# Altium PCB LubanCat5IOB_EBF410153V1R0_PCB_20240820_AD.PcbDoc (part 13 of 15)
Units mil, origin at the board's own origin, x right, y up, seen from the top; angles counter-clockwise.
Board outline 6811.02 x 4055.12 mil, 6 copper layers (TOP, GND02, ART03, ART04, PWR05, BOTTOM), stack 59.279 mil thick; 981 components, 783 nets, 3627 pads, 2669 vias.
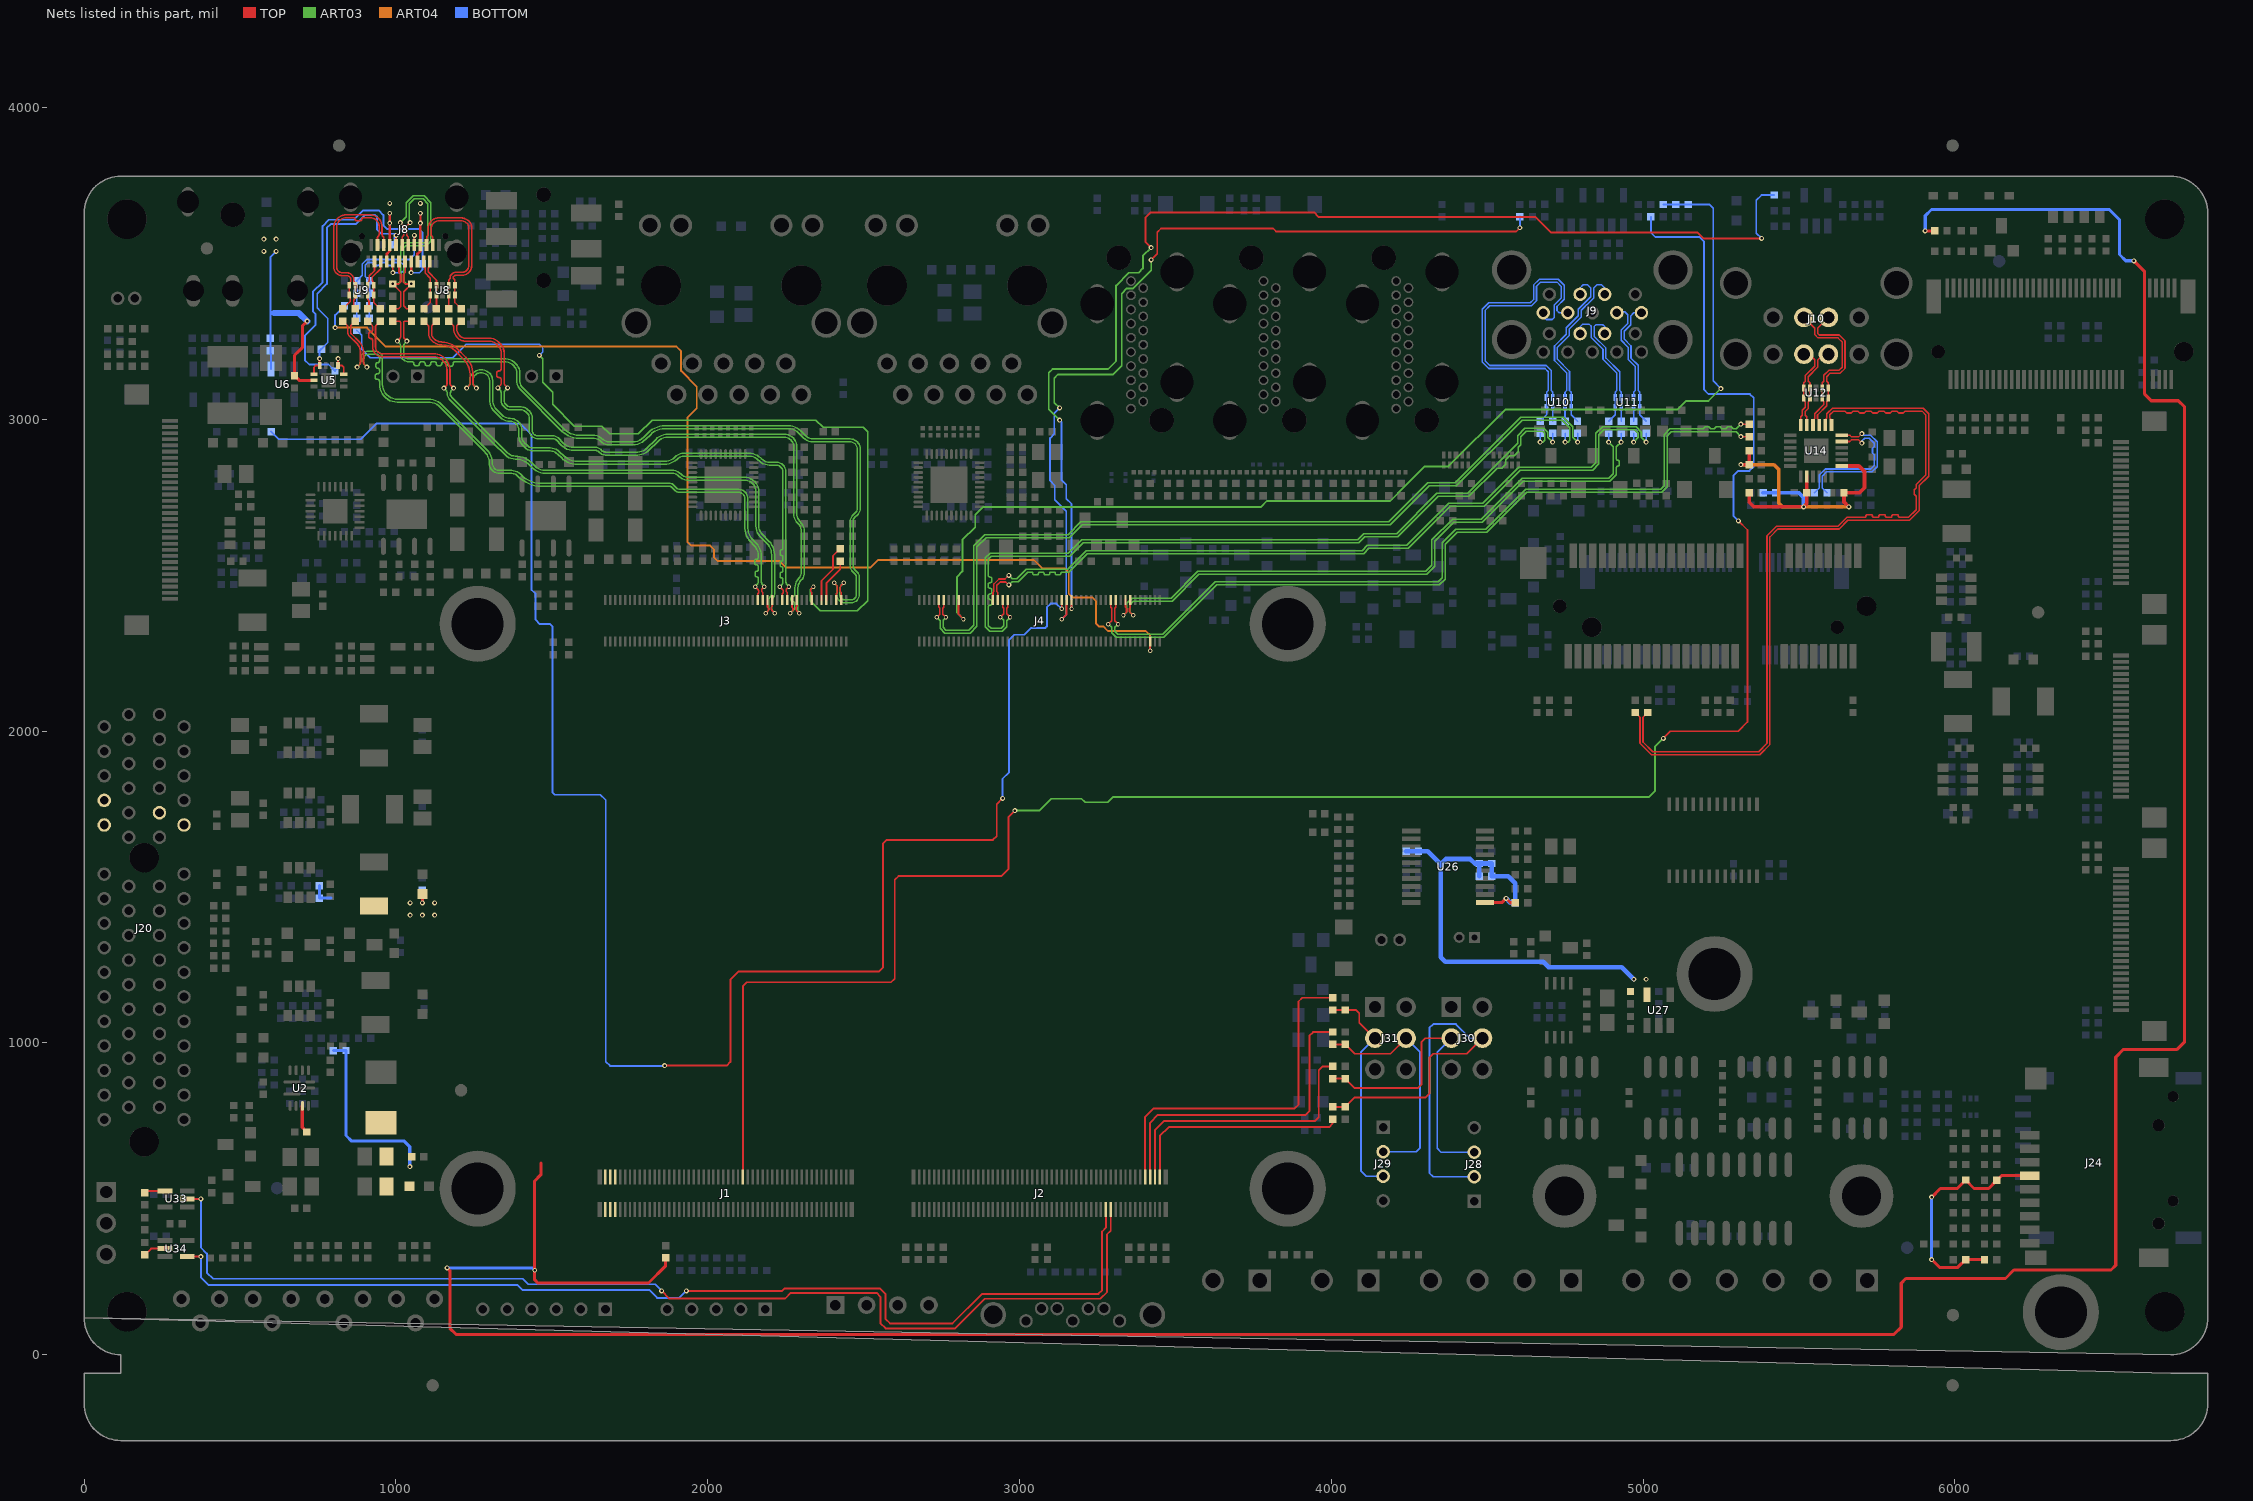
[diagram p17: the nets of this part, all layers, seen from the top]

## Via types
v1: diameter 16, hole 8, TOP to BOTTOM, 2357 vias
v2: diameter 14, hole 8, TOP to BOTTOM, 308 vias
v3: diameter 20, hole 10, TOP to BOTTOM, 4 vias

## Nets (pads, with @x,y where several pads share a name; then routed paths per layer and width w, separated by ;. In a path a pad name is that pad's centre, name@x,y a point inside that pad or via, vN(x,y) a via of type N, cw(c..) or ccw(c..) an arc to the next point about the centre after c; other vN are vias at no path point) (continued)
TYPEC0_SBU2: C85.2 J3.86 | length 2818.1
  TOP w5.2: J3.86@2333.57,2420.74 2333.57,2444.59 2330.39,2447.76 2330.39,2454.48 v2(2339.39,2463.48)
  ART03 w4.5: v1(1460.17,3205) 1470.5,3194.67 1470.5,3119.06 1502.5,3087.06 1502.5,3048.06 1572.06,2978.5 1661.06,2978.5 1686.06,2953.5 1777.94,2953.5 1821.94,2997.5 2347.06,2997.5 2370.06,2974.5 2499.06,2974.5 2513,2960.56 2513,2418 2480.5,2385.5 2361.5,2385.5 2329.44,2417.56 2329.44,2453.53 v2(2339.39,2463.48)
  BOTTOM w5.2: C85.2@875,3284.69 890.3,3269.39 890.3,3224.7 918,3197 1182.29,3197 1225.78,3240.49 1460.15,3240.49 1470.55,3230.09 1470.55,3215.38 v1(1460.17,3205)
TYPEC0_SBU2_DC: J4.95 R94.2 | length 3671.8
  TOP w6: v2(3418.91,2258.14) J4.95@3418.91,2286.88
  ART04 w6: v1(805.32,3294.05) 906.95,3294.05 967.63,3233.37 1900,3233.37 1915,3218.37 1915,3155 1965,3105 1965,3035 1935,3005 1935,2607 1947,2595 2008,2595 2020,2583 2020,2557 2032,2545 2231,2545 2251,2525 2523,2525 2547,2549 3046,2549 3073,2522 3146,2522 3158,2510 3158,2441 3170,2429 3234,2429 3246,2417 3246,2345 3255,2336 3268,2336 3283,2321 3404.91,2321 3418.91,2307 v2(3418.91,2258.14)
  BOTTOM w6: v1(805.32,3294.05) 805.32,3334.37 R94.2@835.32,3364.37
TYPEC0_SSRX1N: J3.80 R86.2 | length 2059.6
  TOP w5.2: R86.2@1210,3314.69 1196.83,3301.52 ccw(c1201.98,3296.37) 1194.7,3296.37 1194.7,3291.75 ccw(c1229.03,3291.75) 1204.76,3267.47 ccw(c1222.8,3285.51) 1222.8,3260 1299.54,3260 cw(c1299.54,3217.13) 1329.85,3247.44 1334.84,3242.45 cw(c1304.53,3212.14) 1347.4,3212.14 1347.4,3116.49 ccw(c1358.84,3116.49) 1350.75,3108.4 v1(1358.15,3101) ; 2285.82,2386.32 v2(2294.15,2378) ; 2285.83,2386.32 cw(c2292.28,2392.78) 2283.15,2392.78 2283.15,2397.61 2286.32,2400.78 J3.80@2286.32,2420.74
  ART03 w4.5: v1(1358.15,3101) 1352.26,3095.11 ccw(c1364.96,3082.41) 1347,3082.41 1347,3060.39 ccw(c1362.41,3060.39) 1351.51,3049.48 1356.92,3044.08 ccw(c1367.82,3054.98) 1367.82,3039.57 1402.55,3039.57 cw(c1402.55,3010.87) 1422.84,3031.16 1428.6,3025.4 cw(c1408.31,3005.11) 1437,3005.12 1437,2966.41 ccw(c1456.41,2966.41) 1456.41,2947 1504.68,2947 cw(c1504.68,2924.5) 1520.59,2940.41 1537.47,2923.53 ccw(c1570.13,2956.18) 1570.13,2910 1640.68,2910 cw(c1640.68,2887.5) 1656.59,2903.41 1660.31,2899.7 ccw(c1671.64,2911.03) 1671.64,2895 1775.37,2895 ccw(c1775.37,2936.52) 1804.72,2907.16 1832.7,2935.14 cw(c1873.41,2894.42) 1873.41,2952 2246.12,2952 cw(c2246.11,2912.62) 2273.96,2940.46 cw(c2246.12,2912.61) 2285.5,2912.62 2285.5,2698.32 ccw(c2321.28,2698.32) 2295.98,2673.02 cw(c2262.14,2639.18) 2310,2639.18 2310,2509.17 cw(c2273.22,2509.17) 2299.23,2483.16 ; v2(2294.15,2378) cw(c2305.37,2389.22) 2289.5,2389.22 2289.5,2459.68 cw(c2322.7,2459.68) 2299.22,2483.15
TYPEC0_SSRX1P: J3.78 R85.2 | length 2095
  TOP w5.2: R85.2@1170,3314.69 1183.17,3301.52 cw(c1178.02,3296.37) 1185.3,3296.37 1185.3,3291.75 ccw(c1229.03,3291.75) 1198.11,3260.83 ccw(c1222.8,3285.51) 1222.8,3250.6 1299.54,3250.6 cw(c1299.54,3217.13) 1323.2,3240.8 1328.2,3235.8 cw(c1304.53,3212.14) 1338,3212.14 1338,3162.49 cw(c1330.5,3162.49) 1330.5,3154.99 ccw(c1330.5,3147.49) 1323,3147.49 1323,3141.69 ccw(c1330.5,3141.69) 1330.5,3134.19 cw(c1330.5,3126.69) 1338,3126.69 1338,3116.49 cw(c1326.56,3116.49) 1334.65,3108.4 v1(1327.25,3101) ; v2(2264.75,2378) 2271.74,2384.99 ccw(c2266.9,2389.84) 2273.75,2389.84 2273.75,2393.71 2270.57,2396.89 J3.78@2270.57,2420.74
  ART03 w4.5: v1(1327.25,3101) 1332.69,3095.55 cw(c1321.08,3083.95) 1337.5,3083.95 1337.5,3060.39 ccw(c1362.41,3060.38) 1344.8,3042.77 1350.2,3037.36 ccw(c1367.82,3054.98) 1367.82,3030.07 1402.55,3030.07 cw(c1402.55,3010.87) 1416.12,3024.44 1421.88,3018.69 cw(c1408.31,3005.11) 1427.5,3005.11 1427.5,2966.41 ccw(c1456.41,2966.41) 1456.41,2937.5 1504.68,2937.5 cw(c1504.68,2924.5) 1513.87,2933.69 1530.76,2916.81 ccw(c1570.13,2956.18) 1570.13,2900.5 1640.68,2900.5 cw(c1640.68,2887.5) 1649.87,2896.69 1653.59,2892.98 ccw(c1671.64,2911.03) 1671.64,2885.5 1775.37,2885.5 ccw(c1775.37,2936.52) 1811.44,2900.44 1839.42,2928.42 cw(c1873.41,2894.42) 1873.41,2942.5 2246.11,2942.5 cw(c2246.11,2912.62) 2267.24,2933.75 cw(c2246.12,2912.61) 2276,2912.61 2276,2698.32 ccw(c2321.28,2698.32) 2289.26,2666.3 cw(c2262.14,2639.18) 2300.5,2639.18 2300.5,2509.17 cw(c2273.22,2509.17) 2292.51,2489.88 ; v2(2264.75,2378) 2276.14,2389.4 ccw(c2266.84,2398.7) 2280,2398.7 2280,2408.2 ccw(c2273.5,2408.2) 2273.5,2414.7 cw(c2273.5,2421.2) 2267,2421.2 2267,2426.2 cw(c2273.5,2426.2) 2273.5,2432.7 ccw(c2273.5,2439.2) 2280,2439.2 2280,2459.68 cw(c2322.7,2459.68) 2292.51,2489.87
TYPEC0_SSRX2N: J3.70 R91.2 | length 2034.3
  TOP w5.2: R91.2@950,3314.69 936.83,3301.52 ccw(c941.98,3296.37) 934.7,3296.37 934.7,3231.87 ccw(c956.17,3231.87) 940.99,3216.69 ccw(c956.17,3231.87) 956.17,3210.4 1121.13,3210.4 cw(c1121.13,3160.99) 1156.07,3195.93 1158.93,3193.07 cw(c1123.99,3158.14) 1173.4,3158.14 1173.4,3114.77 ccw(c1180.68,3114.77) 1175.53,3109.62 v1(1185.15,3100) ; J3.70@2207.58,2420.74 2207.58,2400.78 2204.41,2397.61 2204.41,2392.78 ccw(c2213.54,2392.78) 2207.09,2386.32 v2(2215.41,2378)
  ART03 w4.5: v1(1185.15,3100) 1179.48,3094.33 ccw(c1191.64,3082.18) 1174.45,3082.18 1174.45,3081.31 ccw(c1188.37,3081.31) 1178.53,3071.47 1321.03,2928.97 1357.39,2892.61 ccw(c1383,2918.21) 1383,2882 cw(c1383,2807.16) 1435.92,2860.08 1446.31,2849.7 ccw(c1478.16,2881.55) 1478.16,2836.5 1885.52,2836.5 cw(c1885.52,2795.51) 1914.51,2824.49 ccw(c1939.84,2849.82) 1939.84,2814 2118.09,2814 cw(c2118.09,2768.09) 2164,2768.09 2164,2657.95 ccw(c2202.51,2657.95) 2175.28,2630.72 2196.4,2609.6 cw(c2152.7,2565.9) 2214.5,2565.9 2214.5,2439.37 cw(c2194.43,2439.37) 2208.62,2425.19 ccw(c2216.25,2417.55) 2205.46,2417.55 2205.46,2394.54 ccw(c2221.36,2394.54) 2210.12,2383.29 v2(2215.41,2378)
TYPEC0_SSRX2P: J3.68 R89.2 | length 2046.5
  TOP w5.2: R89.2@910,3314.69 923.17,3301.52 cw(c918.02,3296.37) 925.3,3296.37 925.3,3286.17 cw(c919.15,3286.17) 919.15,3280.02 ccw(c919.15,3273.87) 913,3273.87 913,3265.37 ccw(c919.15,3265.37) 919.15,3259.22 cw(c919.15,3253.07) 925.3,3253.07 925.3,3231.87 ccw(c956.17,3231.87) 934.34,3210.04 ccw(c956.17,3231.87) 956.17,3201 1121.13,3201 cw(c1121.13,3160.99) 1149.42,3189.28 1152.28,3186.42 cw(c1123.99,3158.14) 1164,3158.14 1164,3115.36 cw(c1150.48,3115.36) 1160.04,3105.79 v1(1154.25,3100) ; v2(2186.01,2378) 2193,2384.99 ccw(c2188.16,2389.84) 2195.01,2389.84 2195.01,2393.71 2191.84,2396.89 J3.68@2191.84,2420.74
  ART03 w4.5: v1(1154.25,3100) 1159.92,3094.33 cw(c1147.76,3082.18) 1164.95,3082.18 1164.95,3081.31 ccw(c1188.37,3081.31) 1171.81,3064.76 1314.31,2922.25 1350.68,2885.89 ccw(c1383,2918.21) 1383,2872.5 cw(c1383,2807.16) 1429.2,2853.36 1439.59,2842.98 ccw(c1478.16,2881.55) 1478.16,2827 1885.52,2827 cw(c1885.52,2795.51) 1907.79,2817.78 ; 1907.79,2817.77 ccw(c1939.84,2849.82) 1939.84,2804.5 2118.09,2804.5 cw(c2118.09,2768.09) 2154.5,2768.09 2154.5,2657.95 ccw(c2202.51,2657.95) 2168.56,2624 2189.68,2602.88 cw(c2152.7,2565.9) 2205,2565.9 2205,2439.37 cw(c2194.44,2439.38) 2201.9,2431.9 ccw(c2216.26,2417.55) 2195.96,2417.55 2195.96,2394.54 cw(c2180.06,2394.54) 2191.3,2383.29 v2(2186.01,2378)
TYPEC0_SSTX1N: C80.2 J3.76 | length 1996.9
  TOP w5.2: C80.2@1090,3314.69 1103.17,3301.52 cw(c1098.02,3296.37) 1105.3,3296.37 1105.3,3274.16 ccw(c1133.69,3274.16) 1113.61,3254.09 1116.64,3251.06 ccw(c1146.73,3281.16) 1146.73,3238.6 cw(c1146.74,3179.77) 1188.34,3221.37 1218.12,3191.58 cw(c1170.14,3143.6) 1238,3143.6 1238,3115.49 cw(c1226.56,3115.49) 1234.65,3107.4 v1(1227.25,3100) ; J3.76@2254.83,2420.74 2254.83,2444.59 2251.65,2447.76 2251.65,2451.64 cw(c2258.5,2451.64) 2253.66,2456.48 v2(2260.65,2463.48)
  ART03 w4.5: v1(1227.25,3100) 1232.92,3105.67 ccw(c1220.76,3117.82) 1237.95,3117.82 1237.95,3128.07 cw(c1262.87,3128.07) 1245.25,3145.68 1248.77,3149.2 cw(c1272.78,3125.19) 1272.78,3159.15 cw(c1272.79,3119.31) 1300.95,3147.48 ; 1300.98,3147.46 cw(c1279.2,3125.68) 1310,3125.68 1310,3064.26 ccw(c1357.86,3064.26) 1324.02,3030.42 1340.7,3013.74 ccw(c1366.62,3039.66) 1366.62,3003 cw(c1366.62,2965.62) 1404,2965.62 1404,2944.82 ccw(c1432.54,2944.82) 1412.36,2924.64 1420.64,2916.36 ccw(c1440.82,2936.54) 1440.82,2908 1494.74,2908 cw(c1494.74,2863.92) 1525.91,2895.09 1538.09,2882.91 ccw(c1581.33,2926.15) 1581.33,2865 1861.13,2865 ccw(c1861.13,2912.97) 1895.05,2879.05 cw(c1923.89,2850.21) 1923.89,2891 2133.1,2891 cw(c2133.1,2839.48) 2169.53,2875.91 ; 2169.53,2875.91 2172.08,2873.35 ccw(c2198.28,2899.55) 2198.28,2862.5 2221.82,2862.5 cw(c2221.82,2836.72) 2240.05,2854.95 2243.15,2851.85 cw(c2224.92,2833.61) 2250.7,2833.62 2250.7,2480.01 ccw(c2266.6,2480.01) 2255.36,2468.77 v2(2260.65,2463.48)
TYPEC0_SSTX1P: C79.2 J3.74 | length 1999.6
  TOP w5.2: C79.2@1130,3314.69 1116.83,3301.52 ccw(c1121.98,3296.37) 1114.7,3296.37 1114.7,3274.16 ccw(c1133.69,3274.16) 1120.26,3260.74 1123.29,3257.71 ccw(c1146.73,3281.15) 1146.73,3248 cw(c1146.74,3179.77) 1194.99,3228.02 1224.77,3198.23 cw(c1170.14,3143.6) 1247.4,3143.6 1247.4,3115.49 ccw(c1258.84,3115.49) 1250.75,3107.4 v1(1258.15,3100) ; v2(2231.25,2463.48) 2239.58,2455.15 cw(c2233.12,2448.69) 2242.25,2448.69 2242.25,2443.87 2239.08,2440.7 J3.74@2239.08,2420.74
  ART03 w4.5: v1(1258.15,3100) 1252.48,3105.67 cw(c1264.64,3117.82) 1247.45,3117.82 1247.45,3128.07 cw(c1262.87,3128.07) 1251.96,3138.97 1255.48,3142.49 cw(c1272.78,3125.19) 1272.78,3149.65 cw(c1272.78,3119.31) 1294.24,3140.76 cw(c1279.2,3125.68) 1300.5,3125.68 1300.5,3064.26 ccw(c1357.86,3064.26) 1317.3,3023.7 1333.98,3007.02 ccw(c1366.62,3039.66) 1366.62,2993.5 cw(c1366.62,2965.62) 1394.5,2965.62 1394.5,2944.82 ccw(c1432.54,2944.82) 1405.64,2917.92 1413.92,2909.64 ccw(c1440.82,2936.54) 1440.82,2898.5 1494.74,2898.5 cw(c1494.74,2863.92) 1519.19,2888.37 1531.37,2876.19 ccw(c1581.33,2926.15) 1581.33,2855.5 1861.13,2855.5 ccw(c1861.13,2912.97) 1901.77,2872.33 cw(c1923.89,2850.22) 1923.89,2881.5 2133.1,2881.5 cw(c2133.1,2839.48) 2162.81,2869.19 2165.36,2866.64 ccw(c2198.28,2899.55) 2198.28,2853 2221.82,2853 cw(c2221.82,2836.72) 2233.33,2848.23 2236.43,2845.13 cw(c2224.92,2833.61) 2241.2,2833.61 2241.2,2585.86 cw(c2236.6,2585.86) 2236.6,2581.26 ccw(c2236.6,2576.66) 2232,2576.66 2232,2567.86 ccw(c2236.6,2567.86) 2236.6,2563.26 cw(c2236.6,2558.66) 2241.2,2558.66 2241.2,2549.86 cw(c2236.6,2549.86) 2236.6,2545.26 ccw(c2236.6,2540.66) 2232,2540.66 2232,2531.86 ccw(c2236.6,2531.86) 2236.6,2527.26 cw(c2236.6,2522.66) 2241.2,2522.66 2241.2,2513.86 cw(c2236.6,2513.86) 2236.6,2509.26 ccw(c2236.6,2504.66) 2232,2504.66 2232,2495.86 ccw(c2236.6,2495.86) 2236.6,2491.26 cw(c2236.6,2486.66) 2241.2,2486.66 2241.2,2477.16 cw(c2232.2,2477.16) 2238.57,2470.79 v2(2231.25,2463.48)
TYPEC0_SSTX2N: C83.2 J3.66 | length 2071.9
  TOP w5.2: C83.2@830,3314.69 843.17,3301.52 cw(c838.02,3296.37) 845.3,3296.37 845.3,3280.61 ccw(c865.1,3280.61) 851.1,3266.61 875.76,3241.95 cw(c849.59,3215.78) 886.6,3215.78 886.6,3182.54 cw(c875.16,3182.54) 883.25,3174.45 v1(875.85,3167.05) ; J3.66@2176.09,2420.74 2176.09,2444.59 2172.91,2447.76 2172.91,2451.64 cw(c2179.76,2451.64) 2174.92,2456.48 v2(2181.91,2463.48)
  ART03 w4.5: v1(875.85,3167.05) 881.52,3172.72 ccw(c869.36,3184.87) 886.55,3184.87 886.55,3194 cw(c910.55,3194) 910.55,3218 936.1,3218 cw(c936.1,3197.1) 957,3197.1 957,3112.33 ccw(c1004.83,3112.33) 1004.83,3064.5 1102.84,3064.5 cw(c1102.84,2999.08) 1149.1,3045.34 1290.58,2903.86 cw(c1246.11,2859.39) 1309,2859.39 ccw(c1332.38,2859.39) 1315.85,2842.85 ccw(c1332.39,2859.38) 1332.39,2836 1371.19,2836 cw(c1371.19,2797.83) 1398.18,2824.82 1401.39,2821.61 ccw(c1465.63,2885.84) 1465.63,2795 1875.68,2795 cw(c1875.68,2772.5) 1891.59,2788.41 1900.45,2779.55 ccw(c1911.43,2790.51) 1911.43,2775 2099.17,2775 cw(c2099.17,2745.17) 2129,2745.17 2129,2650.87 ccw(c2181.79,2650.87) 2144.46,2613.54 2155.11,2602.89 cw(c2114.43,2562.21) 2171.96,2562.21 2171.96,2480.01 ccw(c2187.86,2480.01) 2176.62,2468.77 v2(2181.91,2463.48)
TYPEC0_SSTX2P: C82.2 J3.64 | length 2098.1
  TOP w5.2: C82.2@870,3314.69 856.83,3301.52 ccw(c861.98,3296.37) 854.7,3296.37 854.7,3280.61 ccw(c865.1,3280.61) 857.75,3273.25 882.41,3248.59 cw(c849.59,3215.78) 896,3215.78 896,3182.54 ccw(c907.44,3182.54) 899.35,3174.45 v1(906.75,3167.05) ; v2(2152.51,2463.48) 2160.84,2455.15 cw(c2154.38,2448.69) 2163.51,2448.69 2163.51,2443.87 2160.34,2440.7 J3.64@2160.34,2420.74
  ART03 w4.5: v1(906.75,3167.05) 901.08,3172.72 cw(c913.24,3184.87) 896.05,3184.87 896.05,3194 cw(c910.55,3194) 910.55,3208.5 936.1,3208.5 cw(c936.1,3197.1) 947.5,3197.1 947.5,3187.6 cw(c941.75,3187.6) 941.75,3181.85 ccw(c941.75,3176.1) 936,3176.1 936,3169.6 ccw(c941.75,3169.6) 941.75,3163.85 cw(c941.75,3158.1) 947.5,3158.1 947.5,3151.6 cw(c941.75,3151.6) 941.75,3145.85 939.75,3145.85 ccw(c939.75,3140.1) 934,3140.1 934,3133.6 ccw(c939.75,3133.6) 939.75,3127.85 941.75,3127.85 cw(c941.75,3122.1) 947.5,3122.1 947.5,3112.33 ccw(c1004.83,3112.33) 1004.83,3055 1102.84,3055 cw(c1102.84,2999.08) 1142.38,3038.62 1283.86,2897.14 cw(c1246.11,2859.39) 1299.5,2859.39 ccw(c1332.38,2859.39) 1309.13,2836.13 ccw(c1332.38,2859.38) 1332.38,2826.5 1371.19,2826.5 cw(c1371.19,2797.83) 1391.46,2818.1 1394.67,2814.89 ccw(c1465.63,2885.84) 1465.63,2785.5 1875.68,2785.5 cw(c1875.68,2772.5) 1884.87,2781.69 1893.74,2772.83 ccw(c1911.43,2790.51) 1911.43,2765.5 ; 1911.42,2765.5 2099.17,2765.5 cw(c2099.17,2745.17) 2119.5,2745.17 2119.5,2650.87 ccw(c2181.79,2650.86) 2137.74,2606.82 2148.39,2596.17 cw(c2114.43,2562.2) 2162.46,2562.21 2162.46,2556.94 cw(c2156.73,2556.94) 2156.73,2551.21 ccw(c2156.73,2545.48) 2151,2545.48 2151,2538.94 ccw(c2156.73,2538.94) 2156.73,2533.21 cw(c2156.73,2527.48) 2162.46,2527.48 2162.46,2517.98 cw(c2157.23,2517.98) 2157.23,2512.74 ccw(c2157.23,2507.51) 2152,2507.51 2152,2499.98 ccw(c2157.23,2499.98) 2157.23,2494.74 cw(c2157.23,2489.51) 2162.46,2489.51 2162.46,2480.01 cw(c2146.56,2480.01) 2157.81,2468.77 v2(2152.51,2463.48)
TYPEC0_USB20_OTG_DM: J3.98 R82.2 | length 2506.4
  TOP w5.2: R82.2@990,3314.69 1010.1,3314.69 cw(c1010.1,3309.49) 1015.3,3309.49 1015.3,3266.42 cw(c1003.86,3266.42) 1011.95,3258.33 v1(1004.55,3250.92) ; J3.98@2428.06,2420.74 2428.06,2444.59 2424.88,2447.76 2424.88,2457.22 cw(c2442.41,2457.22) 2430.01,2469.61 v2(2435.88,2475.48)
  ART03 w4.5: v1(1004.55,3250.92) 1010.22,3245.25 cw(c998.06,3233.1) 1015.25,3233.1 1015.25,3208.39 ccw(c1036.64,3208.39) 1021.51,3193.26 ccw(c1041.47,3213.22) 1041.47,3185 1050.97,3185 cw(c1050.97,3178.5) 1057.47,3178.5 ccw(c1063.97,3178.5) 1063.97,3172 1068.97,3172 ccw(c1068.97,3178.5) 1075.47,3178.5 cw(c1081.97,3178.5) 1081.97,3185 1086.97,3185 cw(c1086.97,3178.5) 1093.47,3178.5 ccw(c1099.97,3178.5) 1099.97,3172 1104.97,3172 ccw(c1104.97,3178.5) 1111.47,3178.5 cw(c1117.97,3178.5) 1117.97,3185 1122.97,3185 cw(c1122.97,3178.5) 1129.47,3178.5 ccw(c1135.97,3178.5) 1135.97,3172 1140.97,3172 ccw(c1140.97,3178.5) 1147.47,3178.5 cw(c1153.97,3178.5) 1153.97,3185 1158.97,3185 cw(c1158.97,3178.5) 1165.47,3178.5 1165.47,3176.5 ccw(c1171.97,3176.5) 1171.97,3170 1176.97,3170 ccw(c1176.97,3176.5) 1183.47,3176.5 1183.47,3178.5 cw(c1189.97,3178.5) 1189.97,3185 1345.63,3185 cw(c1345.63,3139.13) 1378.07,3171.56 cw(c1355.29,3148.79) 1387.5,3148.79 1387.5,3127.03 ccw(c1435.71,3127.03) 1401.62,3092.94 1532.54,2962.03 ccw(c1586.92,3016.41) 1586.92,2939.5 1630.91,2939.5 cw(c1630.91,2900.5) 1658.49,2928.07 ccw(c1681.6,2951.19) 1681.6,2918.5 1760.49,2918.5 ccw(c1760.49,2976.47) 1801.48,2935.48 1816.64,2950.64 cw(c1862.17,2905.12) 1862.16,2969.5 2259.71,2969.5 cw(c2259.71,2925.2) 2291.04,2956.52 2307.33,2940.23 ccw(c2338.07,2970.96) 2338.07,2927.5 2456.58,2927.5 cw(c2456.58,2904.58) 2479.5,2904.58 2479.5,2711.32 cw(c2466.5,2711.32) 2475.69,2702.13 2464.09,2690.53 ccw(c2480,2674.62) 2457.5,2674.62 2457.5,2527.82 ccw(c2480,2527.82) 2464.09,2511.91 2473.19,2502.81 cw(c2464,2493.61) 2477,2493.61 2477,2437.09 cw(c2460.91,2437.09) 2460.91,2421 2439.54,2421 cw(c2439.54,2436.61) 2423.93,2436.61 2423.93,2455.53 cw(c2443.25,2455.53) 2429.59,2469.19 v2(2435.88,2475.48)
TYPEC0_USB20_OTG_DP: J3.96 R81.2 | length 2470.8
  TOP w5.2: v1(1035.45,3250.92) 1028.05,3258.33 cw(c1036.14,3266.42) 1024.7,3266.42 1024.7,3309.49 cw(c1029.9,3309.49) 1029.9,3314.69 R81.2@1050,3314.69 ; v2(2406.48,2475.48) 2411.35,2470.61 cw(c2401.37,2460.63) 2415.48,2460.63 2415.48,2443.87 2412.31,2440.7 J3.96@2412.31,2420.74
  ART03 w4.5: v1(1035.45,3250.92) 1029.78,3245.25 ccw(c1041.94,3233.1) 1024.75,3233.1 1024.75,3208.39 ccw(c1036.64,3208.39) 1028.23,3199.98 ccw(c1041.47,3213.22) 1041.47,3194.5 1345.63,3194.5 cw(c1345.63,3139.13) 1384.78,3178.28 cw(c1355.29,3148.79) 1397,3148.79 1397,3127.03 ccw(c1435.71,3127.03) 1408.34,3099.66 1539.26,2968.74 ccw(c1586.92,3016.41) 1586.92,2949 1630.91,2949 cw(c1630.91,2900.5) 1665.21,2934.79 ccw(c1681.61,2951.19) 1681.6,2928 1760.49,2928 ccw(c1760.49,2976.47) 1794.76,2942.2 1809.93,2957.36 cw(c1862.16,2905.12) 1862.16,2979 2259.72,2979 cw(c2259.71,2925.2) 2297.76,2963.24 2314.05,2946.95 ccw(c2338.07,2970.96) 2338.07,2937 2456.58,2937 cw(c2456.58,2904.58) 2489,2904.58 2489,2711.32 cw(c2466.5,2711.32) 2482.41,2695.41 2470.81,2683.81 ccw(c2480,2674.61) 2467,2674.61 2467,2527.82 ccw(c2480,2527.82) 2470.81,2518.63 2479.91,2509.53 cw(c2464,2493.61) 2486.5,2493.62 2486.5,2437.09 cw(c2460.91,2437.09) 2460.91,2411.5 2439.54,2411.5 cw(c2439.54,2436.61) 2414.43,2436.61 2414.43,2462.36 ccw(c2401.95,2462.36) v2@2410.77,2471.18 ; v2(2406.48,2475.48) v2@2410.78,2471.18
TYPEC0_USB20_OTG_ID: J3.90 R78.2 | length 189.2
  TOP w6: J3.90@2365.06,2420.74 2365.06,2482.06 2402,2519 2402,2561.68 R78.2@2425.32,2585
TYPEC0_USB20_VBUSDET: J3.92 R77.2 | length 142.7
  TOP w6: J3.92@2380.81,2420.74 2380.81,2473.81 2425.32,2518.32 R77.2@2425.32,2545
TYPEC1_SSRX1N: J4.38 R83.2 | length 2458.9
  TOP w5.2: J4.38@2962.22,2420.74 2962.22,2396.89 2959.04,2393.71 2959.04,2376 v2(2969.8,2365.25)
  ART03 w4.5: v2(2969.8,2365.25) 2958.91,2354.36 2958.91,2333.9 2945,2320 2905.06,2320 2890.5,2334.56 2890.5,2555.44 2906.06,2571 3157,2571 3200,2614 4084.56,2614 4104.06,2633.5 4209.5,2633.5 4338.5,2762.5 4437.5,2762.5 4598,2923 4598,2947.44 4621.06,2970.5 4681.94,2970.5 4693.77,2958.67 4693.77,2943.1 v1(4710,2926.87)
  BOTTOM w5.2: v1(4710,2926.87) R83.2@4710,2954.69
TYPEC1_SSRX1P: J4.36 R84.2 | length 2456.9
  TOP w5.2: v2(2938.89,2365.25) 2949.64,2376 2949.64,2393.71 2946.47,2396.89 J4.36@2946.47,2420.74
  ART03 w4.5: v2(2938.89,2365.25) 2949.41,2354.73 2949.41,2337.84 2941.07,2329.5 2909,2329.5 2900,2338.5 2900,2398.07 cw(c2905.88,2398.07) 2905.88,2403.95 ccw(c2905.88,2409.82) 2911.75,2409.82 2911.75,2416.07 ccw(c2905.88,2416.07) 2905.88,2421.95 cw(c2905.88,2427.82) 2900,2427.82 2900,2434.07 cw(c2905.88,2434.07) 2905.88,2439.95 ccw(c2905.88,2445.82) 2911.75,2445.82 2911.75,2452.07 ccw(c2905.88,2452.07) 2905.88,2457.95 cw(c2905.88,2463.82) 2900,2463.82 2900,2470.07 cw(c2905.88,2470.07) 2905.88,2475.95 ccw(c2905.88,2481.82) 2911.75,2481.82 2911.75,2488.07 ccw(c2905.88,2488.07) 2905.88,2493.95 cw(c2905.88,2499.82) 2900,2499.82 2900,2551.5 2910,2561.5 3160.94,2561.5 3203.94,2604.5 4088.5,2604.5 4108,2624 4213.44,2624 4342.44,2753 4441.44,2753 4532.14,2843.71 4546.71,2843.71 4559.44,2856.43 4559.44,2871 4572.16,2883.73 4586.73,2883.73 4599.45,2896.45 4599.45,2911.02 4607.5,2919.06 4607.5,2943.5 4625,2961 4678,2961 4684.27,2954.73 4684.27,2933.27 4677.87,2926.87 v1(4670,2926.87)
  BOTTOM w5.2: v1(4670,2926.87) R84.2@4670,2954.69
TYPEC1_SSTX1N: C75.2 J4.34 | length 2473.1
  TOP w5.2: J4.34@2930.72,2420.74 2930.72,2444.59 2927.55,2447.76 2927.55,2467.87 2937.95,2478.27 2956.33,2478.27 v1(2965.75,2468.85)
  ART03 w4.5: v1(2965.75,2468.85) 2976.46,2479.55 2995.55,2479.55 3026,2510 3038.38,2510 cw(c3038.38,2505.5) 3042.88,2505.5 ccw(c3047.38,2505.5) 3047.38,2501 3056.38,2501 ccw(c3056.38,2505.5) 3060.88,2505.5 cw(c3065.38,2505.5) 3065.38,2510 3074.38,2510 cw(c3074.38,2505.5) 3078.88,2505.5 ccw(c3083.38,2505.5) 3083.38,2501 3092.38,2501 ccw(c3092.38,2505.5) 3096.88,2505.5 cw(c3101.38,2505.5) 3101.38,2510 3110.38,2510 cw(c3110.38,2505.5) 3114.88,2505.5 ccw(c3119.38,2505.5) 3119.38,2501 3128.38,2501 ccw(c3128.38,2505.5) 3132.88,2505.5 cw(c3137.38,2505.5) 3137.38,2510 3158.44,2510 3217.94,2569.5 4103.5,2569.5 4120,2586 4246.44,2586 4381.44,2721 4490,2721 4606,2837 4838,2837 4858,2857 4858,2950.56 4873.94,2966.5 4973.6,2966.5 4985.25,2954.85 4985.25,2942.12 v1(4970,2926.87)
  BOTTOM w5.2: v1(4970,2926.87) C75.2@4970,2954.69
TYPEC1_SSTX1P: C76.2 J4.32 | length 2474.7
  TOP w5.2: J4.32@2914.97,2420.74 2914.97,2444.59 2918.14,2447.76 2918.14,2471.77 2934.05,2487.67 2953.67,2487.67 v1(2965.75,2499.75)
  ART03 w4.5: v1(2965.75,2499.75) 2976.46,2489.05 2991.61,2489.05 3022.06,2519.5 3154.5,2519.5 3214,2579 4099.56,2579 4116.06,2595.5 4242.5,2595.5 4377.5,2730.5 4486.06,2730.5 4602.06,2846.5 4834.06,2846.5 4848.5,2860.94 4848.5,2954.5 4870,2976 4977.53,2976 4994.75,2958.78 4994.75,2942.12 v1(5010,2926.87)
  BOTTOM w5.2: v1(5010,2926.87) C76.2@5010,2954.69
TYPEC1_USB20_OTG_DM: J4.12 R79.2 | length 2648.4
  TOP w5.2: J4.12@2757.49,2420.74 2757.49,2396.89 2754.32,2393.71 2754.32,2374.9 v2(2764.32,2364.9)
  ART03 w4.5: v2(2764.32,2364.9) 2755.37,2355.95 2755.37,2333 2764.37,2324 2837.56,2324 2853.5,2339.94 2853.5,2594.5 2889,2630 3156,2630 3197,2671 4184.56,2671 4310.06,2796.5 4397.5,2796.5 4607.87,3006.87 4744.5,3006.87 4774.75,2976.62 4774.75,2942.12 v1(4790,2926.87)
  BOTTOM w5.2: v1(4790,2926.87) R79.2@4790,2954.69
TYPEC1_USB20_OTG_DP: J4.10 R80.2 | length 2655
  TOP w5.2: v2(2734.92,2364.9) 2744.92,2374.9 2744.92,2393.71 2741.74,2396.89 J4.10@2741.74,2420.74
  ART03 w4.5: v2(2734.92,2364.9) 2745.87,2353.95 2745.87,2329.06 2760.43,2314.5 2841.5,2314.5 2863,2336 2863,2590.56 2892.94,2620.5 3159.94,2620.5 3200.94,2661.5 4188.5,2661.5 4314,2787 4401.44,2787 4611.81,2997.37 4740.56,2997.37 4765.25,2972.68 4765.25,2932.25 4759.87,2926.87 v1(4750,2926.87)
  BOTTOM w5.2: v1(4750,2926.87) R80.2@4750,2954.69
TYPEC1_USB20_VBUSDET: C253.1 J4.18 R149.1 R150.2 | length 3748.7
  TOP w6: J4.18@2804.73,2420.74 2804.73,2374.75 v2(2820.48,2359)
  ART03 w6: v2(2820.48,2359) 2800,2379.48 2800,2495 2817,2512 2817,2613 2858,2654 2858,2694 2882.43,2718.43 3773.43,2718.43 3793,2738 4189.16,2738 4239,2787.84 4239,2788 4300,2849 4376,2849 4559,3032 5111,3032 5138,3059 5209.94,3059 v1(5249.68,3098.74)
  BOTTOM w6: R150.2@5065,3689.05 R149.1@5105,3689.05 C253.1@5145,3689.05 5213,3689.05 5225,3677.05 5225,3123.42 v1(5249.68,3098.74)
TYPEC_CC1: C78.1 D10.2 J8.A5 U5.10 U5.11 | length 1265.3
  TOP w6: v1(814.53,3194.53) U5.11@814.53,3172.64 826.64,3172.64 832.64,3166.64 U5.10@832.64,3144.68
  TOP w6.8: v1(1049.21,3470.16) J8.A5@1049.21,3506.3
  BOTTOM w6: v1(814.53,3194.53) 814.53,3164.85 C78.1@804.68,3155 783.88,3175.8 722,3175.8 708.32,3189.48 708.32,3268.32 742.12,3302.12 742.12,3337.88 733.63,3346.37 733.63,3408.63 765,3440 765,3619.8 785.2,3640 865.2,3640 895.2,3670 945,3670 960,3655 960,3622 972,3610 1075,3610 1085,3600 1085,3499.69 D10.2@1085.32,3499.37 1085.32,3479.69 1075.79,3470.16 v1(1049.21,3470.16)
TYPEC_CC2: C77.1 D11.2 J8.B5 U5.1 U5.14 | length 875.5
  TOP w6: U5.1@737.36,3144.68 737.36,3166.64 743.36,3172.64 U5.14@755.47,3172.64 v1(755.47,3194.53)
  TOP w6.8: J8.B5@1000.39,3559.05 v1(1000.39,3590.19)
  BOTTOM w6: v1(755.47,3194.53) 755.47,3220.15 C77.1@760.32,3225 781.68,3246.36 781.68,3323.32 757.63,3347.37 ; 757.59,3347.37 747.63,3357.33 747.63,3402.83 779,3434.2 779,3614 791,3626 871,3626 900,3655 934,3655 940,3649 940,3608 953,3595 995.58,3595 v1(1000.39,3590.19) 994.68,3584.47 D11.2@994.68,3559.37
TYPEC_DM: D9.2 J8.A7 J8.B7 R82.1 | length 773.2
  TOP w5.2: R82.1@990,3354.05 1007.68,3354.05 1015.6,3361.97 1015.6,3408.45 v1(990,3434.05) 1009.78,3434.05 1014.98,3439.25 1014.98,3465.33 1009.84,3470.47 J8.A7@1009.84,3506.3 ; J8.B7@1039.76,3559.05 1039.76,3584.87 1034.62,3590.01 1034.62,3620.37 v1(1045.38,3631.12)
  ART03 w4.5: v1(990,3434.05) 1006.25,3434.05 1015.25,3443.05 1015.25,3554.25 1027,3566 1094,3566 1103,3575 1103,3691 1087,3707 1059,3707 1043,3691 1043,3633.5 v1(1045.38,3631.12)
TYPEC_DP: D8.2 J8.A6 J8.B6 R81.1 | length 809.9
  TOP w5.2: v1(1014.47,3631.12) 1025.22,3620.37 1025.22,3590.01 1020.08,3584.87 J8.B6@1020.08,3559.05 ; J8.A6@1029.53,3506.3 1029.53,3470.48 1024.38,3465.33 1024.38,3439.25 1029.59,3434.05 v1(1050,3434.05) 1025,3409.05 1025,3364.37 1035.32,3354.05 R81.1@1050,3354.05
  ART03 w4.5: v1(1014.47,3631.12) 1033.5,3650.16 1033.5,3694.94 1055.06,3716.5 1090.94,3716.5 1112.5,3694.94 1112.5,3571.06 1097.94,3556.5 1030.94,3556.5 1024.75,3550.31 1024.75,3443.05 1033.75,3434.05 v1(1050,3434.05)
TYPEC_SSRXN1: J8.B10 R86.1 U8.5 U8.6 | length 543.6
  TOP w5.2: J8.B10@1098.42,3559.05 1098.42,3581.76 ; 1098.43,3581.76 cw(c1105.95,3581.76) 1100.63,3587.08 1101.36,3587.81 ccw(c1096.04,3593.13) 1103.57,3593.13 1103.57,3611.5 cw(c1138.07,3611.5) 1138.07,3646 1207.94,3646 cw(c1207.94,3607.22) 1235.36,3634.64 cw(c1216.92,3616.2) 1243,3616.2 1243,3492.8 cw(c1212.17,3492.8) 1212.17,3461.97 1192.46,3461.97 ccw(c1192.46,3454.66) 1187.29,3459.83 1184.23,3456.77 1184.23,3452.22 1187.17,3449.28 cw(c1181.85,3443.96) 1189.37,3443.96 U8.6@1189.37,3430.12 U8.5@1189.37,3398.62 1189.37,3374.68 R86.1@1210,3354.05
TYPEC_SSRXN2: J8.A10 R91.1 U9.5 U9.6 | length 174.1
  TOP w5.2: R91.1@950,3354.05 929.37,3374.68 U9.5@929.37,3398.62 U9.6@929.37,3430.12 929.37,3439 924.26,3444.11 924.26,3456.34 951.18,3483.26 J8.A10@951.18,3506.3
TYPEC_SSRXP1: J8.B11 R85.1 U8.4 U8.7 | length 505.7
  TOP w5.2: J8.B11@1118.11,3559.05 1118.11,3581.75 ccw(c1110.59,3581.75) 1115.91,3587.07 1115.17,3587.81 cw(c1120.49,3593.13) 1112.97,3593.13 1112.97,3611.5 cw(c1138.07,3611.5) 1138.07,3636.6 1207.94,3636.6 cw(c1207.94,3607.22) 1228.71,3627.99 cw(c1216.92,3616.2) 1233.6,3616.2 1233.6,3492.8 cw(c1212.17,3492.8) 1212.17,3471.37 1192.46,3471.37 ccw(c1192.46,3454.66) 1180.64,3466.48 1174.83,3460.66 1174.83,3455.34 cw(c1167.31,3455.34) 1172.63,3450.02 1171.89,3449.28 ccw(c1177.21,3443.97) 1169.69,3443.97 U8.7@1169.69,3430.12 U8.4@1169.69,3398.62 1169.69,3354.36 R85.1@1170,3354.05
TYPEC_SSRXP2: J8.A11 R89.1 U9.4 U9.7 | length 164.6
  TOP w5.2: R89.1@910,3354.05 913.91,3357.96 913.91,3380.46 909.69,3384.68 U9.4@909.69,3398.62 U9.7@909.69,3430.12 909.69,3439.06 914.87,3444.23 914.87,3460.24 931.5,3476.87 J8.A11@931.5,3506.3
TYPEC_SSTXN1: C80.1 J8.A3 U8.1 U8.10 | length 169.8
  TOP w5.2: J8.A3@1088.98,3506.3 1088.98,3489.39 1094.15,3484.22 1094.15,3468.92 1110.63,3452.45 U8.10@1110.63,3430.12 U8.1@1110.63,3398.62 1110.63,3374.68 C80.1@1090,3354.05
TYPEC_SSTXN2: C83.1 J8.B3 U9.1 U9.10 | length 571.4
  TOP w5.2: C83.1@830,3354.05 854,3378.05 854,3395.25 U9.1@850.63,3398.62 U9.10@850.63,3430.12 850.63,3434.08 cw(c857.68,3434.08) 852.7,3439.07 853.57,3439.94 ccw(c848.25,3445.26) 855.77,3445.26 855.77,3449.53 ccw(c849.06,3449.53) 853.8,3454.27 850.98,3457.1 ccw(c841.63,3447.75) 841.63,3460.97 828.04,3460.97 cw(c828.04,3488.34) 808.69,3468.99 cw(c827.24,3487.54) 801,3487.54 801,3616.2 cw(c840.57,3616.2) 840.57,3655.77 917.71,3655.77 cw(c917.71,3618) 955.49,3618 955.49,3593.13 ccw(c963.01,3593.13) 957.69,3587.81 958.43,3587.07 cw(c953.11,3581.75) 960.63,3581.75 J8.B3@960.63,3559.05
TYPEC_SSTXP1: C79.1 J8.A2 U8.2 U8.9 | length 165.6
  TOP w5.2: J8.A2@1108.66,3506.3 1108.66,3490.03 1103.56,3484.93 1103.56,3472.81 1130.31,3446.06 U8.9@1130.31,3430.12 U8.2@1130.31,3398.62 1130.31,3354.36 C79.1@1130,3354.05
TYPEC_SSTXP2: C82.1 J8.B2 U9.2 U9.9 | length 545.8
  TOP w5.2: C82.1@870,3354.05 864.59,3359.46 864.59,3381.96 870.31,3387.68 U9.2@870.31,3398.62 U9.9@870.31,3430.12 870.31,3434.11 ccw(c863.19,3434.11) 868.22,3439.15 867.37,3440 cw(c872.69,3445.32) 865.17,3445.32 865.17,3449.53 ccw(c849.05,3449.53) 860.45,3460.92 857.63,3463.74 ccw(c841.63,3447.75) 841.63,3470.37 828.04,3470.37 cw(c828.04,3488.34) 815.33,3475.63 cw(c827.23,3487.54) 810.4,3487.54 810.4,3616.2 cw(c840.57,3616.2) 840.57,3646.37 865.31,3646.37 cw(c865.31,3641.68) 869.99,3641.68 ccw(c874.68,3641.68) 874.68,3637 886.11,3637 ccw(c886.11,3641.68) 890.79,3641.68 cw(c895.48,3641.68) 895.48,3646.37 917.71,3646.37 cw(c917.71,3618) 946.09,3618 946.09,3593.13 cw(c938.56,3593.13) 943.88,3587.81 943.15,3587.07 ccw(c948.47,3581.76) 940.94,3581.76 J8.B2@940.95,3559.05
TYPEC_SUB1: C84.1 D12.2 J8.A8 R92.1 R97.1 | length 421.7
  TOP w5.2: v1(990.16,3470.16) J8.A8@990.16,3506.3
  BOTTOM w5.2: C84.1@915,3324.05 915,3364.05 R92.1@915.32,3364.37 R97.1@915.32,3404.37 D12.2@915.32,3444.37 901.4,3458.29 901.4,3494.27 910.1,3502.97 922.42,3502.97 cw(c922.42,3498.17) 927.23,3498.17 ccw(c932.03,3498.17) 932.03,3493.37 943.23,3493.37 ccw(c943.23,3498.17) 948.03,3498.17 cw(c952.83,3498.17) 952.83,3502.97 964.02,3502.97 cw(c964.02,3498.17) 968.83,3498.17 ccw(c973.63,3498.17) 973.63,3493.37 984.83,3493.37 ccw(c984.83,3498.17) 989.63,3498.17 cw(c994.43,3498.17) 994.43,3502.97 1017,3502.97 1027.4,3492.57 1027.4,3480.56 1017,3470.16 v1(990.16,3470.16)
TYPEC_SUB2: C85.1 D13.2 J8.B8 R94.1 R98.1 | length 454.5
  TOP w5.2: J8.B8@1059.06,3559.05 v1(1059.06,3590.19)
  BOTTOM w5.2: C85.1@875,3324.05 875,3364.05 R94.1@874.68,3364.37 R98.1@874.68,3404.37 D13.2@874.68,3444.37 892,3461.69 892,3498.17 906.21,3512.37 1044.01,3512.37 1059.06,3527.42 v1(1059.06,3590.19)
TYPEC_VBUS_EN: J4.60 R93.1 | length 5981.3
  TOP w6: v1(1862,927) 2061,927 2073,939 2073,1203 2099,1229 2550,1229 2562,1241 2562,1639 2574,1651 2915,1651 2927,1663 2927,1765.74 v1(2945.63,1784.37) ; v2(3135.44,2392) J4.60@3135.44,2420.74
  BOTTOM w6: R93.1@600,2960.32 624.32,2936 887,2936 937.33,2986.33 1398.67,2986.33 1435,2950 1435,2453 1448,2440 1448,2357 1462,2343 1495,2343 1502,2336 1502,1804 1510,1796 1656,1796 1673,1779 1673,940 1687,926 1861,926 v1(1862,927) ; v1(2945.63,1784.37) 2945.63,1846.63 2966,1867 2966,2291 2984,2309 3015.09,2309 3037.09,2331 3083,2331 3088,2336 3088,2397 3100,2409 3118.44,2409 v2(3135.44,2392)
UART2_RX: R291.2 U34.2 | length 72.9
  TOP w6: R291.2@195,320.32 215,340.31 U34.2@259.57,340.31
UART2_RX_M0_DEBUG: J2.78 U34.4 | length 3441.9
  TOP w6: U34.4@330.43,314.72 v1(374.72,314.72) ; v1(1931.32,204.63) 2238.63,204.63 2246,212 2553,212 2570,195 2570,115 2585,100 2785,100 2880,195 3253,195 3265,207 3265,395 3277.17,407.17 J2.78@3277.17,465.62
  BOTTOM w6: v1(374.72,314.72) 374.72,248.65 400,223.37 1390.63,223.37 1406,208 1812,208 1838,182 1908.69,182 v1(1931.32,204.63)
UART2_TX: R290.2 U33.4 | length 66.9
  TOP w6: R290.2@195,519.68 200.6,525.28 U33.4@259.57,525.28
UART2_TX_M0_DEBUG: J2.80 U33.2 | length 3632.5
  TOP w6: U33.2@330.43,499.69 v1(374.69,499.69) ; v1(1852.58,204.63) 1877.21,180 2248,180 2266,198 2542,198 2554.25,185.75 2554.25,100.75 2570.75,84.25 2794.25,84.25 2889.25,179.25 3259.52,179.25 3280.75,200.48 3280.75,385.75 3292.92,397.92 J2.80@3292.92,465.62
  BOTTOM w6: v1(374.69,499.69) 374.69,343.69 394,324.37 394,263.37 414,243.37 1406.63,243.37 1424,226 1831.21,226 v1(1852.58,204.63)
UART4_RX: D64.1 J28.3 J30.3 R297.2 | length 1034.4
  TOP w6: R297.2@4005,885.32 D64.1@4045,885.32 4075.32,855 4278,855 4290,867 4290,1003 4302,1015 J30.3@4385,1015
  BOTTOM w6: J30.3@4385,1015 4340,970 4340,661.37 4352,649.37 J28.3@4458.62,649.37
UART4_RX_M2: J2.97 R297.1 | length 893.2
  TOP w6: J2.97@3434.65,569.96 3434.65,719.65 3465,750 3948,750 3960,762 3960,912.68 3972,924.68 R297.1@4005,924.68
UART4_TX: D63.1 J28.2 J30.4 R298.2 | length 1446.8
  TOP w6: R298.2@4005,794.68 D63.1@4045,794.68 4075.32,825 4303,825 4315,837 4315,953 4327,965 4435,965 J30.4@4485,1015
  BOTTOM w6: J28.2@4458.62,570.63 4327,570.63 4315,582.63 4315,1048 4327,1060 4400,1060 4445,1015 J30.4@4485,1015
UART4_TX_M2: J2.99 R298.1 | length 716.2
  TOP w6: J2.99@3450.4,569.96 3450.4,701.4 3479,730 3993,730 4005,742 R298.1@4005,755.32
UART7_RX: D62.1 J29.3 J31.3 R299.2 | length 712.4
  TOP w6: R299.2@4005,1105.32 D62.1@4045,1105.32 4079.68,1105.32 4090,1095 4090,1065 J31.3@4140,1015
  BOTTOM w6: J31.3@4140,1015 4095,970 4095,590 4112.84,572.16 J29.3@4166.38,572.16
UART7_RX_M2: J2.93 R299.1 | length 1146.8
  TOP w6: J2.93@3403.16,569.96 3403.16,763.16 3430,790 3883,790 3895,802 3895,1132.68 3907,1144.68 R299.1@4005,1144.68
UART7_TX: D61.1 J29.2 J31.4 R300.2 | length 762.6
  TOP w6: R300.2@4005,995.32 D61.1@4045,995.32 4075.32,965 4190,965 J31.4@4240,1015
  BOTTOM w6: J29.2@4166.38,650.9 4273,650.9 4285,662.9 4285,970 J31.4@4240,1015
UART7_TX_M2: J2.95 R300.1 | length 1022.1
  TOP w6: J2.95@3418.9,569.96 3418.9,743.9 3444,769 3918,769 3930,781 3930,1022.68 3942,1034.68 R300.1@4005,1034.68
USB20_DM1: J9.11 R88.1 U11.2 U11.9 | length 400.9
  BOTTOM w5.2: J9.11@4876.84,3274.86 4876.84,3297.37 4870.84,3303.37 4849,3303.37 4843,3297.37 4843,3266.37 4881,3228.37 4881,3196.37 4925.17,3152.2 4925.17,3092.22 4930.31,3087.08 U11.2@4930.31,3070.12 U11.9@4930.31,3038.62 4930.31,2994.36 R88.1@4930,2994.05
USB20_DP1: J9.12 R90.1 U11.1 U11.10 | length 412.2
  BOTTOM w5.2: J9.12@4798.04,3274.86 4798.04,3296.41 4806,3304.37 4828,3304.37 4833.6,3298.77 4833.6,3262.48 4871.6,3224.48 4871.6,3192.48 4915.77,3148.31 4915.77,3092.22 4910.63,3087.08 U11.1@4910.63,3070.12 U11.10@4910.63,3038.62 4910.63,3014.68 R90.1@4890,2994.05
USB20_HOST0_DM: J4.88 R88.2 | length 2025.2
  TOP w5.2: J4.88@3355.92,2420.74 3355.92,2396.89 3352.74,2393.71 3352.74,2383 v2(3364.5,2371.25)
  ART03 w4.5: v2(3364.5,2371.25) 3353.79,2381.95 3353.79,2405.79 3365,2417 3490,2417 3575.5,2502.5 4306.5,2502.5 4332,2528 4332,2609 4393,2670 4485,2670 4615.87,2800.87 4893.87,2800.87 4914.75,2821.75 4914.75,2845.55 cw(c4919.38,2845.55) 4919.38,2850.17 ccw(c4919.38,2854.8) 4924,2854.8 4924,2863.55 ccw(c4919.38,2863.55) 4919.38,2868.17 cw(c4919.38,2872.8) 4914.75,2872.8 4914.75,2911.62 v1(4930,2926.87)
  BOTTOM w5.2: v1(4930,2926.87) R88.2@4930,2954.69
USB20_HOST0_DP: J4.86 R90.2 | length 2013.8
  TOP w5.2: v2(3333.59,2371.25) 3343.34,2381 3343.34,2393.71 3340.17,2396.89 J4.86@3340.17,2420.74
  ART03 w4.5: v2(3333.59,2371.25) 3344.29,2381.95 3344.29,2409.73 3361.06,2426.5 3486.06,2426.5 3571.56,2512 4302.56,2512 4322.5,2531.94 4322.5,2612.94 4389.06,2679.5 4481.06,2679.5 4611.93,2810.37 4889.93,2810.37 4905.25,2825.69 4905.25,2911.62 v1(4890,2926.87)
  BOTTOM w5.2: v1(4890,2926.87) R90.2@4890,2954.69
USB20_HOST1_DM: J4.82 R107.2 | length 2606.5
  TOP w5.2: J4.82@3308.67,2420.74 3308.67,2396.89 3305.5,2393.71 3305.5,2353.9 v2(3316.25,2343.15) ; v1(5314,2984.37) R107.2@5340.32,2984.37
  ART03 w4.5: v2(3316.25,2343.15) 3305.55,2332.44 3305.55,2319.45 3315,2310 3459.56,2310 3628.56,2479 4343,2479 4355.5,2491.5 4355.5,2603.5 4399.5,2647.5 4495.06,2647.5 4623.43,2775.87 5056.5,2775.87 5067.5,2786.87 5067.5,2950.5 5086.12,2969.12 5193,2969.12 5199.25,2975.37 5211,2975.37 5217.25,2969.12 5229,2969.12 5235.25,2975.37 5247,2975.37 5253.25,2969.12 5265,2969.12 5271.25,2975.37 5283,2975.37 5289.25,2969.12 5298.75,2969.12 v1(5314,2984.37)
USB20_HOST1_DP: J4.80 R106.2 | length 2606.7
  TOP w5.2: v2(3285.34,2343.15) 3296.1,2353.9 3296.1,2393.71 3292.92,2396.89 J4.80@3292.92,2420.74 ; v1(5314,2944.37) R106.2@5340.32,2944.37
  ART03 w4.5: v2(3285.34,2343.15) 3296.05,2332.44 3296.05,2315.52 3311.06,2300.5 3463.5,2300.5 3632.5,2469.5 4346.94,2469.5 4365,2487.56 4365,2599.56 4403.44,2638 4499,2638 4627.37,2766.37 5060.44,2766.37 5077,2782.93 5077,2946.56 5090.06,2959.62 5298.75,2959.62 v1(5314,2944.37)
USB20_HOST_PWR_EN: J1.57 R324.1 | length 6546.1
  TOP w6: J1.57@2113.09,569.96 2113.09,1182.25 2125.09,1194.25 2588,1194.25 2600,1206.25 2600,1523 2612,1535 2942,1535 2965,1558 2965,1725 v1(2985,1745) ; v1(5065,1976.62) 5087.75,1999.37 5305,1999.37 5335,2029.37 5335,2645 v1(5305.63,2674.37)
  ART03 w6: v1(2985,1745) 3064,1745 3102,1783 3199,1783 3210.33,1771.67 3283.67,1771.67 3301,1789 5020,1789 5038,1807 5038,1949.62 v1(5065,1976.62)
  BOTTOM w6: R324.1@5025,3649.69 5025,3599.37 5040,3584.37 5181.4,3584.37 5195,3570.77 5195,3096 5210,3081 5343,3081 5355,3069 5355,2847.97 5341.4,2834.37 5305,2834.37 5289.92,2819.29 5289.92,2690.08 v1(5305.63,2674.37)
USB20_HUB_PWR_EN: J4.64 R102.1 | length 3791.1
  TOP w6: v2(3166.94,2392) J4.64@3166.94,2420.74 ; v1(3422.52,3550.63) 3403.88,3569.27 3403.88,3645.88 3421.37,3663.37 3945,3663.37 3959,3649.37 4654,3649.37 4704,3599.37 5173.63,3599.37 5193,3580 v1(5380.32,3580)
  ART03 w6: v1(3128.65,2997.17) 3094,3031.82 3094,3149 3106,3161 3284,3161 3310,3187 3310,3429 3351,3470 3382,3470 3396,3484 3396,3524.11 v1(3422.52,3550.63)
  BOTTOM w6: v1(3128.65,2997.17) 3135,2990.82 3135,2805 3150,2790 3150,2745.38 3166.94,2728.44 v2(3166.94,2392) ; v1(5380.32,3580) 5362.92,3597.4 5362.92,3701.97 5380.32,3719.37 R102.1@5420.32,3719.37
USB30_DM: J9.2 R79.1 U10.5 U10.6 | length 565.5
  BOTTOM w5.2: R79.1@4790,2994.05 4769.37,3014.68 U10.6@4769.37,3038.62 U10.5@4769.37,3070.12 4769.37,3087.08 4764.23,3092.22 4764.23,3153.43 4725.4,3192.26 4725.4,3231.48 4763,3269.08 4763,3289.37 4802,3328.37 4802,3349.37 4842,3389.37 4842,3420.97 4852.4,3431.37 4866.44,3431.37 4876.84,3420.97 J9.2@4876.84,3400.86
USB30_DP: J9.3 R80.1 U10.4 U10.7 | length 557.6
  BOTTOM w5.2: R80.1@4750,2994.05 4749.69,2994.36 U10.7@4749.69,3038.62 U10.4@4749.69,3070.12 4749.69,3087.08 4754.83,3092.22 4754.83,3149.54 4716,3188.37 4716,3235.37 4753.6,3272.97 4753.6,3293.26 4792.6,3332.26 4792.6,3353.26 4832.6,3393.26 4832.6,3421.37 4822.2,3431.77 4808.44,3431.77 4798.04,3421.37 J9.3@4798.04,3400.86
USB30_OTG_PWR_EN: J4.62 R96.1 | length 2821.3
  TOP w6: v2(3135.44,2359) 3151.19,2374.75 J4.62@3151.19,2420.74 ; v1(3422.52,3511.26) 3442,3530.74 3442,3599.97 3454,3611.97 3813.4,3611.97 3823,3602.37 4593,3602.37 v1(4605,3614.37)
  ART03 w6: v1(3128.65,3036.54) 3111.65,3053.54 3111.65,3132 3123.65,3144 3301,3144 3328,3171 3328,3403 3344.82,3419.82 3364.94,3419.82 3422.52,3477.4 v1(3422.52,3511.26)
  BOTTOM w6: v1(3128.65,3036.54) 3111.65,3019.54 3111.65,2953.28 3098,2939.63 3098,2803 3113.37,2787.63 3113.37,2741.63 3150.04,2704.96 3150.04,2373.6 v2(3135.44,2359)
  BOTTOM w6.8: v1(4605,3614.37) R96.1@4605,3649.69
USB30_RXN: J9.5 R83.1 U10.2 U10.9 | length 1030.1
  BOTTOM w5.2: J9.5@4679.94,3341.77 4679.94,3329.06 4689,3320 4709,3320 4714.64,3325.64 4714.64,3365.77 4738.14,3389.26 4738.14,3426.03 4724.05,3440.12 4671.48,3440.12 4658.4,3427.03 4658.4,3380.48 4642.29,3364.37 4508.6,3364.37 4493.4,3349.17 4493.4,3187.57 4508.6,3172.37 4689.26,3172.37 4705.17,3156.46 4705.17,3092.22 4710.31,3087.08 U10.2@4710.31,3070.12 U10.9@4710.31,3038.62 4710,3038.31 R83.1@4710,2994.05
USB30_RXP: J9.6 R84.1 U10.1 U10.10 | length 1030.5
  BOTTOM w5.2: R84.1@4670,2994.05 4690.63,3014.68 U10.10@4690.63,3038.62 U10.1@4690.63,3070.12 4690.63,3087.08 4695.77,3092.22 4695.77,3152.57 4685.37,3162.97 4504.71,3162.97 4484,3183.68 4484,3353.06 4504.71,3373.77 4638.4,3373.77 4649,3384.37 4649,3430.93 4667.59,3449.52 4727.94,3449.52 4747.53,3429.93 4747.53,3385.37 4724.04,3361.88 4724.04,3348.96 4731.23,3341.77 J9.6@4758.74,3341.77
USB30_TXN: C75.1 J9.8 U11.4 U11.7 | length 411.2
  BOTTOM w5.2: J9.8@4916.14,3341.77 4919.74,3345.37 4941,3345.37 4950.84,3335.53 4950.84,3307.11 4930,3286.26 4930,3253.37 4952,3231.37 4952,3192.37 4974.83,3169.54 4974.83,3092.22 4969.69,3087.08 U11.4@4969.69,3070.12 U11.7@4969.69,3038.62 4969.69,2994.36 C75.1@4970,2994.05
USB30_TXP: C76.1 J9.9 U11.5 U11.6 | length 414.2
  BOTTOM w5.2: J9.9@4994.94,3341.77 4970.64,3341.77 4960.24,3331.37 4960.24,3303.21 4939.4,3282.37 4939.4,3257.26 4961.4,3235.26 4961.4,3196.26 4984.23,3173.43 4984.23,3092.22 4989.37,3087.08 U11.5@4989.37,3070.12 U11.6@4989.37,3038.62 4989.37,3014.68 C76.1@5010,2994.05
USB_HUB_3V3: C94.1 C95.1 C96.1 R100.2 R101.2 R104.2 R105.2 U14.1 U14.20 | length 1270.1
  TOP w12: v1(5314,2854.37) R101.2@5340.32,2854.37 R105.2@5340.32,2899.37 ; R104.2@5340.32,2764.37 5340.32,2734.05 5355,2719.37 v1(5515,2719.37) 5524.68,2729.05 C95.1@5524.68,2764.37 5525.47,2765.16 U14.20@5525.47,2816.69 ; U14.1@5637.68,2850.16 5692.21,2850.16 5710,2832.37 5710,2780.37 5694,2764.37 C96.1@5644.68,2764.37 5644.68,2734.69 v1(5660,2719.37)
  ART04 w12: v1(5314,2854.37) 5419.63,2854.37 5435,2839 5435,2731.37 5447,2719.37 v1(5515,2719.37) v1(5660,2719.37)
  BOTTOM w12: R100.2@5385,2764.05 C94.1@5425,2764.05 5500.32,2764.05 5515,2749.37 v1(5515,2719.37)
USB_HUB_DM1: J10.2 U12.2 U12.9 U14.11 | length 272.6
  TOP w5.2: U14.11@5525.47,2982.05 5525.47,3007.87 5520.33,3013.01 5520.33,3024.7 5530.02,3034.39 5530.02,3054.15 5530,3055.37 5535.31,3060.68 U12.2@5535.31,3068.62 U12.9@5535.31,3100.12 5535.31,3117.08 5530.17,3122.22 5530.17,3136.93 5559.82,3166.58 5559.82,3189.19 5579.29,3208.66 J10.2@5594.49,3208.66
USB_HUB_DM2: J10.8 U12.5 U12.6 U14.9 | length 494.9
  TOP w5.2: U14.9@5564.84,2982.05 5564.84,2997.53 5559.7,3002.67 5559.7,3014.07 5589.27,3043.64 5589.27,3056.64 5594.37,3061.74 U12.5@5594.37,3068.62 U12.6@5594.37,3100.12 5594.37,3117.08 5589.23,3122.22 5589.23,3136.93 5599.63,3147.33 5631.96,3147.33 5647.87,3163.24 5647.87,3251.51 5629,3270.37 5565.02,3270.37 5559.82,3275.57 5559.82,3292.1 J10.8@5594.49,3326.77
USB_HUB_DM3: R269.2 U14.7 | length 2431.7
  TOP w5.2: R269.2@5015,2059.69 4999.7,2044.39 4999.7,1964.77 5030.7,1933.77 5370.77,1933.77 5397.6,1960.6 5397.6,2626.6 5428.37,2657.37 5625,2657.37 5653,2685.37 5710.5,2685.37 ccw(c5710.5,2689.87) 5715,2689.87 cw(c5719.5,2689.87) 5719.5,2694.37 5731.3,2694.37 cw(c5731.3,2689.87) 5735.8,2689.87 ccw(c5740.3,2689.87) 5740.3,2685.37 5752.1,2685.37 ccw(c5752.1,2689.87) 5756.6,2689.87 cw(c5761.1,2689.87) 5761.1,2694.37 5772.9,2694.37 cw(c5772.9,2689.87) 5777.4,2689.87 ccw(c5781.9,2689.87) 5781.9,2685.37 5793.7,2685.37 ccw(c5793.7,2689.87) 5798.2,2689.87 cw(c5802.7,2689.87) 5802.7,2694.37 5814.5,2694.37 cw(c5814.5,2689.87) 5819,2689.87 ccw(c5823.5,2689.87) 5823.5,2685.37 5851,2685.37 5876,2710.37 5876,2753.18 5870,2759.18 5870,2773.98 5876,2779.98 5876,2790.66 5907,2821.66 5907,3013.97 5894.6,3026.37 5840.56,3026.37 5834.56,3020.37 5819.77,3020.37 5813.77,3026.37 5798.97,3026.37 5792.97,3020.37 5778.16,3020.37 5772.16,3026.37 5757.36,3026.37 5751.36,3020.37 5736.56,3020.37 5730.56,3026.37 5715.77,3026.37 5709.77,3020.37 5694.97,3020.37 5688.97,3026.37 5674.16,3026.37 5668.16,3020.37 5653.36,3020.37 5647.36,3026.37 5611.27,3026.37 5599.07,3014.17 5599.07,3004.3 5604.21,2999.16 U14.7@5604.21,2982.05
USB_HUB_DM4: R143.1 U14.5 | length 456.6
  TOP w5.2: U14.5@5637.68,2928.9 5663.5,2928.9 5668.64,2934.04 5691,2934.04 v1(5701.75,2923.29)
  BOTTOM w5.2: R143.1@5550,2764.05 5565.3,2779.35 5565.3,2821.26 5584.81,2840.77 5730.4,2840.77 5741.51,2851.88 5741.51,2886.46 5736,2891.97 5736,2907.26 5741.51,2912.77 5741.51,2923.64 5725.48,2939.66 5711.29,2939.66 5701.75,2930.12 v1(5701.75,2923.29)
USB_HUB_DP1: J10.3 U12.1 U12.10 U14.12 | length 273.5
  TOP w5.2: U14.12@5505.79,2982.05 5505.79,3007.87 5510.93,3013.01 5510.93,3028.59 5520.62,3038.28 5520.62,3050.25 5520.6,3055.77 5515.63,3060.74 U12.1@5515.63,3068.62 U12.10@5515.63,3100.12 5515.63,3117.08 5520.77,3122.22 5520.77,3140.82 5550.42,3170.47 5550.42,3190.95 5532.71,3208.66 J10.3@5515.75,3208.66
USB_HUB_DP2: J10.9 U12.4 U12.7 U14.10 | length 494.9
  TOP w5.2: J10.9@5515.75,3326.77 5550.42,3292.1 5550.42,3271.68 5561.12,3260.97 5625.11,3260.97 5638.47,3247.61 5638.47,3167.13 5628.06,3156.73 5595.73,3156.73 5579.83,3140.82 5579.83,3122.22 5574.69,3117.08 U12.7@5574.69,3100.12 U12.4@5574.69,3068.62 5574.69,3061.68 5579.86,3056.51 5579.86,3047.53 5550.3,3017.96 5550.3,3002.67 5545.16,2997.53 U14.10@5545.16,2982.05
USB_HUB_DP3: R270.2 U14.8 | length 2433.3
  TOP w5.2: R270.2@4975,2059.69 4990.3,2044.39 4990.3,1960.88 5026.81,1924.37 5374.66,1924.37 5407,1956.71 5407,2622.71 5432.26,2647.97 5628.89,2647.97 5656.89,2675.97 5854.89,2675.97 5885.4,2706.48 5885.4,2786.77 5916.4,2817.77 5916.4,3017.86 5898.49,3035.77 5607.38,3035.77 5589.67,3018.06 5589.67,3004.04 5584.53,2998.9 U14.8@5584.53,2982.05
USB_HUB_DP4: R142.1 U14.6 | length 458.9
  TOP w5.2: U14.6@5637.68,2948.58 5663.5,2948.58 5668.64,2943.44 5691,2943.44 v1(5701.75,2954.19)
  BOTTOM w5.2: R142.1@5590,2764.05 5574.7,2779.35 5574.7,2817.37 5588.7,2831.37 5734.29,2831.37 5750.91,2847.98 5750.91,2927.53 5729.38,2949.06 5706.89,2949.06 v1(5701.75,2954.19)
VBUS5V0_TYPEC: C74.1 C87.1 C88.1 J8.A4 J8.A9 J8.B4 J8.B9 U5.2 U6.1 | length 1079.2
  TOP w6.8: v1(980.32,3629.37) v1(980.32,3660.86) ; v1(1078.74,3629.37) v1(1078.74,3660.86)
  TOP w8: J8.A9@970.87,3506.3 970.87,3530.4 980.32,3539.85 J8.B4@980.32,3559.05 v1(980.32,3629.37) ; J8.A4@1069.29,3506.3 1069.29,3530.4 1078.74,3539.85 J8.B9@1078.74,3559.05 v1(1078.74,3629.37)
  TOP w10: v1(715.42,3314.69) 700,3299.27 700,3230 675,3205 C74.1@675,3139.68 689.68,3125 U5.2@737.36,3125
  BOTTOM w6: U6.1@599.6,3161.58 599.6,3210.09 597.32,3212.37 C88.1@597.32,3220.37 C87.1@597.32,3260.37 597.32,3519.97 v1(615.98,3538.63)
  BOTTOM w20: 610,3341 689.11,3341 v1(715.42,3314.69)
  other v1: 576.61,3538.63 576.61,3578 615.98,3578 980.32,3692.35 1078.74,3692.35
VCC3V3_PCIECLK: C162.1 C163.1 C168.1 C186.1 C187.1 R223.1 R224.1 R225.1 R226.1 R235.1 U26.1 U27.5 | length 1624.5
  TOP w10: U26.1@4493.11,1449.84 4546.73,1449.84 v1(4560.63,1463.74) 4575,1449.37 C163.1@4590.32,1449.37
  BOTTOM w15: C168.1@4240,1614.68 R235.1@4280,1614.68 4309.68,1614.68 4351,1573.36 ; R225.1@4475,1534.68 R223.1@4475,1575.32 ; v1(4560.63,1463.74) 4574.37,1450 C162.1@4590.32,1450 4590.32,1512 4567.64,1534.68 R226.1@4515,1534.68 R224.1@4515,1575.32 R223.1@4475,1575.32 ; v1(4970.69,1204.06) 4931.75,1243 4697,1243 4680,1260 4366,1260 4351,1275 4351,1573.36 ; 4351,1573.36 4367.25,1589.61 4446.02,1589.61 4460.31,1575.32 R223.1@4475,1575.32
  other v1: 5010.06,1204.06
VCC3V3_PCIEX4: C180.1 C193.1 C194.2 J20.A9 J20.A10 J20.B8 J20.B10 L17.2 R249.2 | length 105.8
  TOP w10: v1(1085,1449.37) C180.1@1085,1477.87
  BOTTOM w10: C194.2@754.68,1504.37 R249.2@754.68,1464.37 792,1464.37
  other v1: 1045.63,1410 1085,1410 1124.37,1410 1045.63,1449.37 1124.37,1449.37
VCC3V3_SD_S3: C9.1 C10.1 D23.1 J24.4 R285.2 | length 755.9
  TOP w10: v1(5925.63,305) 5950.63,280 6009.68,280 C9.1@6034.68,305 R285.2@6095.32,305 ; v1(5925.63,505) 5953.63,533 6007.68,533 C10.1@6034.68,560 6061.68,533 6108.39,533 D23.1@6134.68,559.29 6149.68,574.29 J24.4@6240.06,574.29
  BOTTOM w10: v1(5925.63,305) v1(5925.63,505)
VCC4V0_SYS: C20.2 C21.1 C22.1 C23.1 C24.1 C27.1 J1.1 J1.2 J1.3 J1.4 J1.5 J1.6 L3.2 R11.1 R12.1 R362.1 U2.5 | length 11971.7
  TOP w10: U2.5@699.84,797.95 699.84,729.21 C27.1@714.68,714.37 ; v1(1164.05,278.51) 1173,269.56 1173,85.23 1193,65.23 5804.86,65.23 5828,88.37 5828,229.37 5843,244.37 6162.37,244.37 6189.37,271.37 6501,271.37 6516,286.37 6516,954.37 6541,979.37 6713,979.37 6737,1003.37 6737,3039.37 6717,3059.37 6630,3059.37 6608.76,3080.61 6608.76,3473.61 v1(6574,3508.37) ; 1465,615 1465,577 1444.98,556.98 v2(1444.98,271) 1444.98,239.81 1454.98,229.81 1810.19,229.81 1865,284.63 R362.1@1865,310.32 ; v1(5905,3604.37) R11.1@5935.32,3604.37
  BOTTOM w10: R12.1@799.68,975.04 839.68,975.04 C20.2@840,975.36 840,703 858,685 1027,685 1044.63,667.37 v1(1044.63,603) ; v1(1164.05,278.51) 1437.47,278.51 v2(1444.98,271) ; v1(5905,3604.37) 5905,3653 5925,3673 6495.37,3673 6528,3640.37 6528,3528.37 6548,3508.37 v1(6574,3508.37)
